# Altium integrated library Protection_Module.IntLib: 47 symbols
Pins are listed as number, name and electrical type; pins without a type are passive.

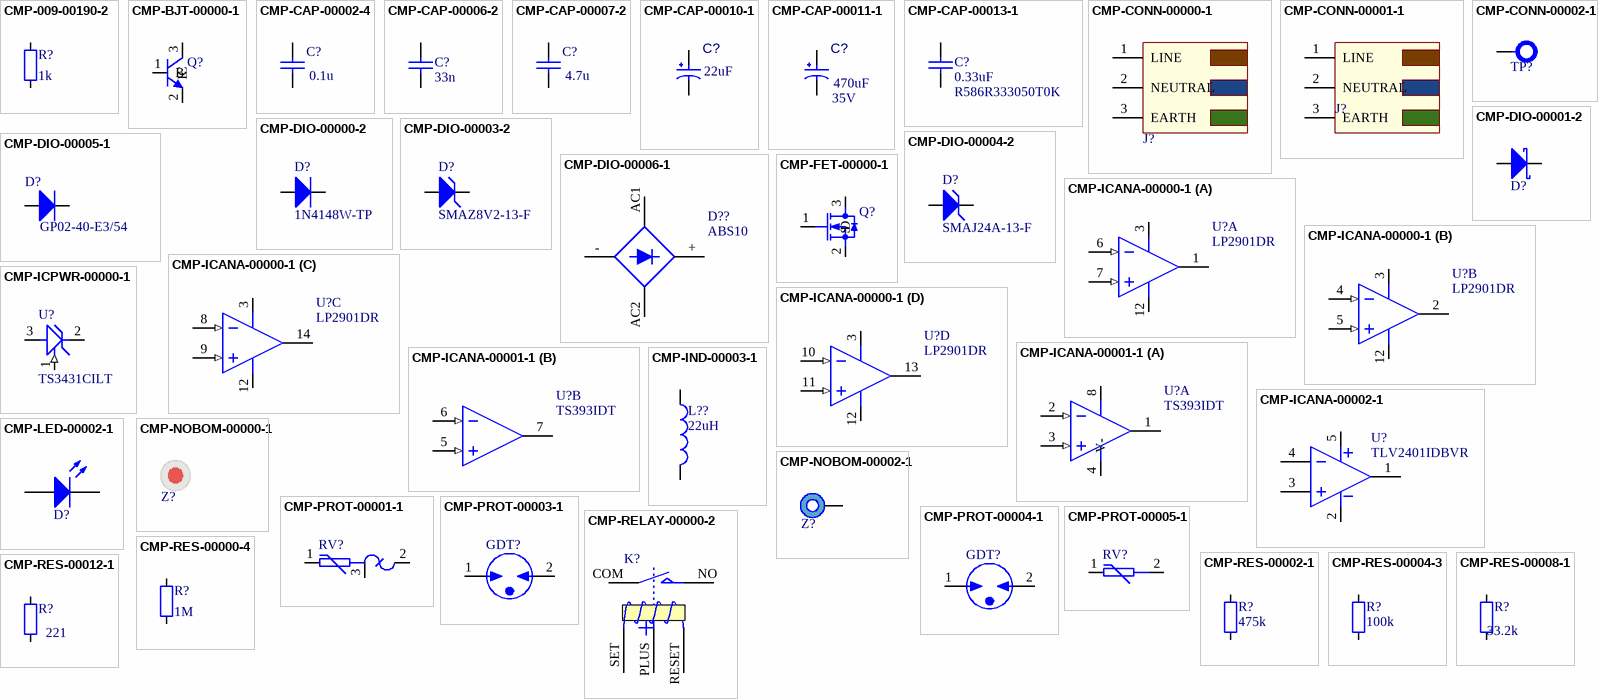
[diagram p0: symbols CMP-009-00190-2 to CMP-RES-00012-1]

## CMP-009-00190-2
designator R?, comment value 1k  (hidden comment: ERJ-3EKF1001V)
Res Thick Film 0603 1K Ohm 1% 1/10W ±100ppm/°C Molded SMD Punched Carrier T/R; Manufacturer: Panasonic; Voltage Rating: 75V; Power: 100mW
footprint RESC1608X05AN,0603, (Chip Resistor, Body 1.6x0.8mm, IPC Medium Density, 0603 imperial with minimal silk)
footprint RESC1608X60,0603,L (Chip Resistor, Body 1.6x0.8mm, IPC High Density, 0603 imperial)
footprint RESC1608X05AN[0603] (Chip Resistor, Body 1.6x0.8mm, IPC Medium Density, 0603 imperial with silk box)
pins: 1, 2
1 alternate drawing of the same symbol

## CMP-BJT-00000-1
designator Q?, comment BCV72,215  (value not drawn)
BCV72 Series 60 V 100 mA 250 mW NPN SMT General Purpose Transistor - SOT-23; Manufacturer: Nexperia; Collector Emitter Voltage (VCEO): 60V; Collector Base Voltage (VCBO): 80V; Frequency: 100MHz; Max Collector Current: 100mA
footprint SOT95P275X125-3N (SOT23, 3-Leads, Body 2.90x2.75mm, Pitch 0.95mm, IPC Medium Density)
pins: 1 B, 2 E, 3 C

## CMP-CAP-00002-4
designator C?, comment value 0.1u  (hidden comment: CL10B104KB8NNNL)
Multilayer Ceramic Capacitor, 0.1 uF, 50 V, ± 10%, X7R, 0603 [1608 Metric]; Manufacturer: Samsung; Voltage Rating: 50V; Material: 4241
footprint CAPC1608X09N,0603, (Chip Capacitor, Body 1.6x0.8mm, IPC Medium Density, 0603 imperial with minimal silk)
footprint CAPC1608X100N,0603,L (Chip Capacitor, Body 1.6x0.8mm, IPC High Density, 1.0 mm height, 0603 imperial)
footprint CAPC1608X09N[0603] (Chip Capacitor, Body 1.6x0.8mm, IPC Medium Density, 0603 imperial with silk box)
pins: 1, 2

## CMP-CAP-00006-2
designator C?, comment value 33n  (hidden comment: CL10B333KB8NNNC)
Multilayer Ceramic Capacitor, 0.033 uF, 50 V, ± 10%, X7R, 0603 [1608 Metric]; Manufacturer: Samsung; Voltage Rating: 50V
footprint CAPC1608X09N,0603, (Chip Capacitor, Body 1.6x0.8mm, IPC Medium Density, 0603 imperial with minimal silk)
footprint CAPC1608X100N,0603,L (Chip Capacitor, Body 1.6x0.8mm, IPC High Density, 1.0 mm height, 0603 imperial)
footprint CAPC1608X09N[0603] (Chip Capacitor, Body 1.6x0.8mm, IPC Medium Density, 0603 imperial with silk box)
pins: 1, 2

## CMP-CAP-00007-2
designator C?, comment value 4.7u  (hidden comment: CL10A475KA8NQNC)
Multilayer Ceramic Capacitor, 4.7 uF, 25 V, ± 10%, X5R, 0603 [1608 Metric]; Manufacturer: Samsung; Voltage Rating: 25V; Dielectric: X7R
footprint CAPC1608X09N,0603, (Chip Capacitor, Body 1.6x0.8mm, IPC Medium Density, 0603 imperial with minimal silk)
footprint CAPC1608X100N,0603,L (Chip Capacitor, Body 1.6x0.8mm, IPC High Density, 1.0 mm height, 0603 imperial)
footprint CAPC1608X09N[0603] (Chip Capacitor, Body 1.6x0.8mm, IPC Medium Density, 0603 imperial with silk box)
pins: 1, 2

## CMP-CAP-00010-1
designator C?, comment value 22uF  (hidden comment: ESH226M035AC3AA)
Cap Aluminum Lytic 22uF 35V 20% (5 X 11mm) Radial 2mm 65mA 2000h 105C Bulk; Manufacturer: KEMET; Life (Hours): 2000Hour
footprint CAP_RAD2P_CYL_5X13 (Radial electrolytic 2 mm pitch 5 mm dia 12.5 mm high with + and - terminals.)
pins: +, -

## CMP-CAP-00011-1
designator C?, comment value 470uF  Voltage Rating (DC): 35V  (hidden comment: ESH477M035AH3AA)
Capacitor; Al Electrolytic; Cap 470 uF; Tol 20%; Vol-Rtg 35 VDC; Radial; 10x17 mm; Manufacturer: KEMET; Dissipation Factor: 0.14%; Life (Hours): 2000Hour
footprint CAP_RAD5P_CYL_10X20 (Radial electrolytic 5 mm pitch 10 mm dia, 20 mm high with + and - terminals.)
pins: +, -

## CMP-CAP-00013-1
designator C?, comment R586R333050T0K  value 0.33uF
CAP FILM 600VAC(X1) 0.33 UF 10%; Manufacturer: KEMET
footprint CAP_RAD28P3213X22 (Box capacitor 27.5 mm pin pitch, 31.5 mm length, 13 mm width, 22 mm height)
pins: 1, 2

## CMP-CONN-00000-1
designator J?, comment 703W-00/54  (value not drawn)
Conn Electrical Power Inlet Right Angled Pin Cont 3 Cond 3 Poles Solder 250V; Manufacturer: Qualtek
footprint QUALTEK_703W-00/54 (Mains power inlet IEC 320-C14 with 9 mm pin pitch.)
pins: 1 LINE, 2 NEUTRAL, 3 EARTH

## CMP-CONN-00001-1
designator J?, comment PX0675/PC  (value not drawn)
Conn Electrical Power Outlet Right Angled Pin Cont 3 Cond 3 Poles Solder 250V; Manufacturer: Bulgin
footprint BULGIN_PX0675/PC (Mains power inlet IEC 320-F (like a C13, but panel mount) with 7 mm pin pitch.)
pins: 1 LINE, 2 NEUTRAL, 3 EARTH

## CMP-CONN-00002-1
designator TP?, comment KEYSTONE_5010  (value not drawn)
Through hole test point, red; Manufacturer: Keystone Electronics; Manufacturer Part Number: 5010; Hole Diameter: 1.6mm
footprint KEYSTONE_5010 (TEST POINT PC MULTIPURPOSE RED)
pins: 1

## CMP-DIO-00000-2
designator D?, comment 1N4148W-TP
Rectifier Diode Switching 100V 0.3A 4ns 2-Pin SOD-123 T/R / DIODE GEN PURP 100V 150MA SOD123; Manufacturer: MCC; Forward Voltage: 1V; Power Dissipation: 400mW
footprint SOD-123 (SOD-123 SMD diode with A and K pads)
pins: A, K

## CMP-DIO-00001-2
designator D?, comment MBR130T1G  (value not drawn)
DIODE SCHOTTKY 30V 1A SOD123 / Rectifier Diode Schottky 30V 1A 2-Pin SOD-123 T/R; Manufacturer: ON Semiconductor; Power Dissipation: 400mW; Reverse Recovery Time: 4ns; Forward Voltage: 470mV
footprint SOD-123 (SOD-123 SMD diode with A and K pads)
pins: A, K

## CMP-DIO-00003-2
designator D?, comment SMAZ8V2-13-F
DIODE ZENER 8.2V 1W SMA; Manufacturer: Diodes; Reverse Recovery Time: 1.8us; Forward Current: 1A; Forward Voltage: 1.2V
footprint DO-214AC (SMA Molded Diode, 2-Leads, Body 4.30x2.61mm, IPC Medium Density with A and K pads)
pins: A, K

## CMP-DIO-00004-2
designator D?, comment SMAJ24A-13-F
SMAJ24A Series 400 W 24 V Surface Mount Uni-Directional TVS Diode - DO-214AC; Manufacturer: Diodes; Forward Current: 1A; Power Dissipation: 400W; Forward Voltage: 1.2V; Reverse Recovery Time: 1.8us; Voltage Rating (DC): 24V
footprint DO-214AC (SMA Molded Diode, 2-Leads, Body 4.30x2.61mm, IPC Medium Density with A and K pads)
pins: A, K

## CMP-DIO-00005-1
designator D?, comment GP02-40-E3/54
Rectifier Diode Switching 4KV 0.25A 2000ns 2-Pin DO-41 T/R / DIODE GEN PURP 4KV 250MA DO204; Manufacturer: Vishay; Reverse Recovery Time: 2usec; Forward Voltage: 3V; Voltage Rating (DC): 4000V
footprint DO-204AL (TH diode (DO-41), 10.16 mm pitch, with A and K pads)
pins: A, K

## CMP-DIO-00006-1
designator D??, comment ABS10
Bridge Rectifier Abs/Sopa-4 T&r 5K Rohs Compliant: Yes; Manufacturer: SMC; Manufacturer Part Number: ABS10TR; Manufacturer: Diotec; Manufacturer: Diodes; Manufacturer Part Number: ABS10A-13
footprint SOP400P640X170-4N_BRIDGE (Bridge Rectifier SOPA-4, SOP, 4-Leads, Body 5.05x4.40mm, Pitch 4.00mm, IPC Medium Density)
pins: +, -, AC1, AC2

## CMP-FET-00000-1
designator Q?, comment IRLML6346TRPBF  (value not drawn)
MOSFET Transistor, N Channel, 3.4 A, 30 V, 0.046 ohm, 4.5 V, 800 mV; Manufacturer: Infineon; Drain to Source Voltage (Vdss): 30V; Continuous Drain Current (ID): 3.4A; Drain to Source Resistance: 46mR
footprint SOT95P275X125-3N (SOT23, 3-Leads, Body 2.90x2.75mm, Pitch 0.95mm, IPC Medium Density)
pins: 1 G, 2 S, 3 D

## CMP-ICANA-00000-1
designator U?, comment LP2901DR
Quad low-power industrial grade standard comparator 14-SOIC -40 to 85; Manufacturer: Texas Instruments; Min Supply Voltage: 3V; Max Supply Voltage: 30V
footprint SOIC127P600X175-14N (SOIC, 14-Leads, Body 8.65x3.90mm, Pitch 1.27mm, IPC Medium Density, SO-14)
part A pins: 1 OUT1, 3 V+ (power), 6 IN1- (in), 7 IN1+ (in), 12 V- (power)
part B pins: 2 OUT2, 3 V+ (power), 4 IN2- (in), 5 IN2+ (in), 12 V- (power)
part C pins: 3 V+ (power), 8 IN3- (in), 9 IN3+ (in), 12 V- (power), 14 OUT3
part D pins: 3 V+ (power), 10 IN4- (in), 11 IN4+ (in), 12 V- (power), 13 OUT4

## CMP-ICANA-00001-1
designator U?, comment TS393IDT
Micropower CMOS dual voltage comparator, 9µA, 16V, -40, 0 to 125, 70°C, SO-8, Tape and Reel; Manufacturer: STMicroelectronics; Min Supply Voltage: 2.7V
footprint SOIC127P600X175-8N (SOIC, 8-Leads, Body 4.90x3.90mm, Pitch 1.27mm, IPC Medium Density, SO-8)
part A pins: 1 OUT1, 2 IN1- (in), 3 IN1+ (in), 4 V- (power), 8 V+ (power)
part B pins: 5 IN2+ (in), 6 IN2- (in), 7 OUT2

## CMP-ICANA-00002-1
designator U?, comment TLV2401IDBVR
Op Amp Single Low Power Amplifier R-R I/O ±8V/16V 5-Pin SOT-23 T/R; Manufacturer: Texas Instruments; Bandwidth: 5.5kHz; Max Supply Voltage: 16V; Min Supply Voltage: 2.5V
footprint SOT95P280X145-5N (SOT23, 5-Leads, Body 2.90x2.80mm, Pitch 0.95mm, IPC Medium Density)
pins: 1 OUT, 2 -Vs, 3 +IN, 4 -IN, 5 +Vs

## CMP-ICPWR-00000-1
designator U?, comment TS3431CILT
V-Ref Adjustable 1.24V to 24V 100mA 3-Pin SOT-23 T/R; Manufacturer: STMicroelectronics; Max Supply Voltage: 25V; Tolerance: 0.25%
footprint SOT95P275X125-3N (SOT23, 3-Leads, Body 2.90x2.75mm, Pitch 0.95mm, IPC Medium Density)
pins: 1 VREF (in), 2 K, 3 A

## CMP-IND-00003-1
designator L??, comment value 22uH  (hidden comment: SRP1265CC-220M)
Inductor Power Shielded Wirewound 22uH 20% 100KHz 20Q-Factor Carbonyl Powder 10A 0.037Ohm DCR; Manufacturer: Bourns
footprint INDUCTOR-BOURNS_SRP1265CC (SMT inductor 12 mm square, 6.5 mm high, with 4.7 mm wide terminals)
pins: 1, 2
1 alternate drawing of the same symbol

## CMP-LED-00002-1
designator D?, comment LTST-C191KRKT  (value not drawn)
LED Uni-Color Red 639nm 2-Pin Chip LED T/R / LED RED CLEAR 0603 SMD; Manufacturer: Vishay Lite-On; Forward Voltage: 2V; Forward Current: 30mA; Viewing Angle: 130°
footprint LEDC1608X06NRED,0603, (Chip LED Body 1.6x0.8mm, IPC Medium Density, red)
pins: A, K

## CMP-NOBOM-00000-1
designator Z?, comment FIDUCIAL_1_3  (value not drawn)  (no BOM)
Fiducial 1 mm copper, 3 mm solder mask, two footprint options.
footprint FIDUCIAL_1_3_KEEPOUT (1mm dia fiducial with 3mm dia keepout)
footprint FIDUCIAL_1_3 (1mm dia fiducial with 3mm dia solder mask opening)

## CMP-NOBOM-00002-1
designator Z?, comment MOUNTING_HOLE_5MM  (value not drawn)  (no BOM)
5 mm diameter plated mounting hole with 8 mm diameter copper surround
footprint MOUNT_HOLE_5MM_8MM (Hole sized for a 5 mm screw, with 8 mm copper surrounding.)
pins: 0

## CMP-PROT-00001-1
designator RV?, comment TMOV20RP300M  (value not drawn)
Var MOV 300VAC/385VDC 10000A 517V Radial Bulk; Manufacturer: Littelfuse; Varistor Voltage: 470V; Clamping Voltage: 775V; Voltage Rating (AC): 300V
footprint LITTELFUSE_ITMOV_20MM (MOV with thermal fusing and indicator lead)
pins: 1, 2, 3

## CMP-PROT-00003-1
designator GDT?, comment CG32.5L  (value not drawn)
Arrestor; 2500 V (min.) (breakdown); Rugged Ceramic-metal Package; 1 Pf (max.); Manufacturer: Littelfuse; Breakdown Voltage: 2.5kV
footprint LITTELFUSE_CG3x (for gas discharge tubes and other wide axial components)
pins: 1, 2

## CMP-PROT-00004-1
designator GDT?, comment CG31.0L  (value not drawn)
CG3 Series - Two Terminal High Voltage Gas Plasma Arresters, 1000V, 10kA, plug in, RoHS; Manufacturer: Littelfuse; Breakdown Voltage: 1.0kV
footprint LITTELFUSE_CG3x (for gas discharge tubes and other wide axial components)
pins: 1, 2

## CMP-PROT-00005-1
designator RV?, comment TMOV20RP300E  (value not drawn)
Thermally Protected Varistor 300 V RMS 775 V Clamp 10000 A 800 pF Radial Lead; Manufacturer: Littelfuse; Manufacturer: Eaton; Manufacturer Part Number: MOVTP20V300N; Voltage Rating (AC): 300V; Varistor Voltage: 517V
footprint MOV_RAD7.5P5.5S_DISC_20X11.5 (MOV radial disc, 7.5 mm pitch with 5.5 mm offset, 20 mm dia. 11.5 mm thick, max height 26 mm.)
pins: 1, 2

## CMP-RELAY-00000-2
designator K?, comment TE_CONN_2-1415898-5  (value not drawn)
Electromechanical Relay SPST-NO 16A 12VDC 240Ohm Through Hole; Manufacturer: TE Connectivity P&B; Contact Voltage Rating (AC): 250V; Coil Power: 600mW; Throw Configuration: SPST
footprint TE_RT1_2COIL_LATCHING (TE Connectivity/Schrack RT1/RT3 type latching SPST relay)
pins: COM, NO, PLUS, RESET, SET

## CMP-RES-00000-4
designator R?, comment value 1M  (hidden comment: ERJ-3EKF1004V)
Res Thick Film 0603 1M Ohm 1% 1/10W ±100ppm/°C Molded SMD Punched Carrier T/R; Manufacturer: Panasonic; Voltage Rating (DC): 75V; Max Power Dissipation: 100mW
footprint RESC1608X05AN,0603, (Chip Resistor, Body 1.6x0.8mm, IPC Medium Density, 0603 imperial with minimal silk)
footprint RESC1608X60,0603,L (Chip Resistor, Body 1.6x0.8mm, IPC High Density, 0603 imperial)
footprint RESC1608X05AN[0603] (Chip Resistor, Body 1.6x0.8mm, IPC Medium Density, 0603 imperial with silk box)
pins: 1, 2
1 alternate drawing of the same symbol

## CMP-RES-00002-1
designator R?, comment value 475k  (hidden comment: ERJ-3EKF4753V)
SMD Chip Resistor, 475 kOhm, ± 1%, 100 mW, 0603 [1608 Metric], Thick Film, Precision; Manufacturer: Panasonic; Max Power Dissipation: 100mW; Voltage Rating: 75V; Temperature Coefficient: 100ppm/°C
footprint RESC1608X05AN,0603, (Chip Resistor, Body 1.6x0.8mm, IPC Medium Density, 0603 imperial with minimal silk)
footprint RESC1608X60,0603,L (Chip Resistor, Body 1.6x0.8mm, IPC High Density, 0603 imperial)
footprint RESC1608X05AN[0603] (Chip Resistor, Body 1.6x0.8mm, IPC Medium Density, 0603 imperial with silk box)
pins: 1, 2
1 alternate drawing of the same symbol

## CMP-RES-00004-3
designator R?, comment value 100k  (hidden comment: ERJ-3EKF1003V)
Resistor Thick Film 0603 100K Ohm 1% 1/10W 100ppm/C Molded SMD Punched Carrier T/R; Manufacturer: Panasonic; Max Power Dissipation: 100mW; Voltage Rating (DC): 75V; Temperature Coefficient: 100ppm/°C
footprint RESC1608X05AN,0603, (Chip Resistor, Body 1.6x0.8mm, IPC Medium Density, 0603 imperial with minimal silk)
footprint RESC1608X60,0603,L (Chip Resistor, Body 1.6x0.8mm, IPC High Density, 0603 imperial)
footprint RESC1608X05AN[0603] (Chip Resistor, Body 1.6x0.8mm, IPC Medium Density, 0603 imperial with silk box)
pins: 1, 2
1 alternate drawing of the same symbol

## CMP-RES-00008-1
designator R?, comment value 33.2k  (hidden comment: ERJ-3EKF3322V)
Res Thick Film 0603 33.2K Ohm 1% 1/10W +/-100ppm/ßC Molded SMD Punched Carrier T/R; Manufacturer: Panasonic; Voltage Rating: 50V; Power: 100mW; Temperature Coefficient: 100ppm/°C
footprint RESC1608X05AN,0603, (Chip Resistor, Body 1.6x0.8mm, IPC Medium Density, 0603 imperial with minimal silk)
footprint RESC1608X60,0603,L (Chip Resistor, Body 1.6x0.8mm, IPC High Density, 0603 imperial)
footprint RESC1608X05AN[0603] (Chip Resistor, Body 1.6x0.8mm, IPC Medium Density, 0603 imperial with silk box)
pins: 1, 2
1 alternate drawing of the same symbol

## CMP-RES-00012-1
designator R?, comment value 221  (hidden comment: ERJ-3EKF2210V)
SMD Chip Resistor, 221 Ohm, ± 1%, 100 mW, 0603 [1608 Metric], Thick Film, Precision; Manufacturer: Panasonic; Temperature Coefficient: 100ppm/°C; Voltage Rating: 75V; Power Rating: 100mW
footprint RESC1608X05AN,0603, (Chip Resistor, Body 1.6x0.8mm, IPC Medium Density, 0603 imperial with minimal silk)
footprint RESC1608X60,0603,L (Chip Resistor, Body 1.6x0.8mm, IPC High Density, 0603 imperial)
footprint RESC1608X05AN[0603] (Chip Resistor, Body 1.6x0.8mm, IPC Medium Density, 0603 imperial with silk box)
pins: 1, 2
1 alternate drawing of the same symbol

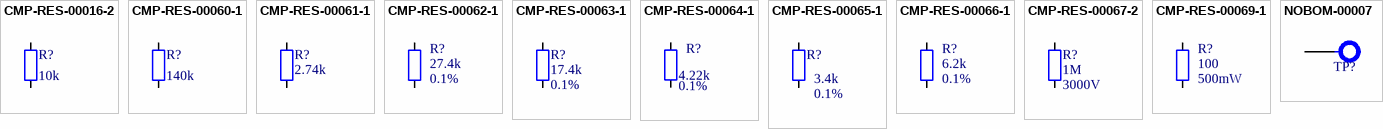
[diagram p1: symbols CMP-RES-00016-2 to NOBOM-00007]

## CMP-RES-00016-2
designator R?, comment value 10k  (hidden comment: RMCF0603FT10K0)
Res Thick Film 0603 10K Ohm 1% 1/10W ±100ppm/°C Molded SMD SMD Paper T/R; Manufacturer: Stackpole Electronics; Max Power Dissipation: 100mW; Voltage Rating (DC): 75V
footprint RESC1608X05AN,0603, (Chip Resistor, Body 1.6x0.8mm, IPC Medium Density, 0603 imperial with minimal silk)
footprint RESC1608X60,0603,L (Chip Resistor, Body 1.6x0.8mm, IPC High Density, 0603 imperial)
footprint RESC1608X05AN[0603] (Chip Resistor, Body 1.6x0.8mm, IPC Medium Density, 0603 imperial with silk box)
pins: 1, 2
1 alternate drawing of the same symbol

## CMP-RES-00060-1
designator R?, comment value 140k  (hidden comment: RMCF0603FT140K)
Res Thick Film 0603 140K Ohm 1% 1/10W ±100ppm/°C Molded SMD SMD Paper T/R; Manufacturer: Stackpole Electronics; Voltage Rating (DC): 75V; Power: 100mW
footprint RESC1608X05AN,0603, (Chip Resistor, Body 1.6x0.8mm, IPC Medium Density, 0603 imperial with minimal silk)
footprint RESC1608X60,0603,L (Chip Resistor, Body 1.6x0.8mm, IPC High Density, 0603 imperial)
footprint RESC1608X05AN[0603] (Chip Resistor, Body 1.6x0.8mm, IPC Medium Density, 0603 imperial with silk box)
pins: 1, 2
1 alternate drawing of the same symbol

## CMP-RES-00061-1
designator R?, comment value 2.74k  (hidden comment: RMCF0603FT2K74)
Res Thick Film 0603 2.74K Ohm 1% 1/10W ±100ppm/°C Molded SMD SMD Paper T/R; Manufacturer: Stackpole Electronics; Voltage Rating: 75V; Power Rating: 100mW
footprint RESC1608X05AN,0603, (Chip Resistor, Body 1.6x0.8mm, IPC Medium Density, 0603 imperial with minimal silk)
footprint RESC1608X60,0603,L (Chip Resistor, Body 1.6x0.8mm, IPC High Density, 0603 imperial)
footprint RESC1608X05AN[0603] (Chip Resistor, Body 1.6x0.8mm, IPC Medium Density, 0603 imperial with silk box)
pins: 1, 2
1 alternate drawing of the same symbol

## CMP-RES-00062-1
designator R?, comment value 27.4k  Tolerance: 0.1%  (hidden comment: ERA-3AEB2742V)
Res Thin Film 0603 27.4K Ohm 0.1% 0.1W(1/10W) ±25ppm/C Pad SMD Automotive T/R; Manufacturer: Panasonic; Power: 100mW; Temperature Coefficient: 25ppm/°C; Voltage Rating: 75V
footprint RESC1608X05AN,0603, (Chip Resistor, Body 1.6x0.8mm, IPC Medium Density, 0603 imperial with minimal silk)
footprint RESC1608X60,0603,L (Chip Resistor, Body 1.6x0.8mm, IPC High Density, 0603 imperial)
footprint RESC1608X05AN[0603] (Chip Resistor, Body 1.6x0.8mm, IPC Medium Density, 0603 imperial with silk box)
pins: 1, 2
1 alternate drawing of the same symbol

## CMP-RES-00063-1
designator R?, comment value 17.4k  Tolerance: 0.1%  (hidden comment: ERA-3AEB1742V)
Res Thin Film 0603 17.4K Ohm 0.1% 0.1W(1/10W) ±25ppm/C Pad SMD Automotive T/R; Manufacturer: Panasonic; Max Power Dissipation: 100mW; Voltage Rating (DC): 75V; Temperature Coefficient: 25ppm/°C
footprint RESC1608X05AN,0603, (Chip Resistor, Body 1.6x0.8mm, IPC Medium Density, 0603 imperial with minimal silk)
footprint RESC1608X60,0603,L (Chip Resistor, Body 1.6x0.8mm, IPC High Density, 0603 imperial)
footprint RESC1608X05AN[0603] (Chip Resistor, Body 1.6x0.8mm, IPC Medium Density, 0603 imperial with silk box)
pins: 1, 2
1 alternate drawing of the same symbol

## CMP-RES-00064-1
designator R?, comment value 4.22k  Tolerance: 0.1%  (hidden comment: ERA-3AEB4221V)
Res Thin Film 0603 4.22K Ohm 0.1% 1/10W ±25ppm/°C Molded SMD SMD Punched Carrier T/R; Manufacturer: Panasonic; Max Power Dissipation: 100mW; Voltage Rating: 75V
footprint RESC1608X05AN,0603, (Chip Resistor, Body 1.6x0.8mm, IPC Medium Density, 0603 imperial with minimal silk)
footprint RESC1608X60,0603,L (Chip Resistor, Body 1.6x0.8mm, IPC High Density, 0603 imperial)
footprint RESC1608X05AN[0603] (Chip Resistor, Body 1.6x0.8mm, IPC Medium Density, 0603 imperial with silk box)
pins: 1, 2
1 alternate drawing of the same symbol

## CMP-RES-00065-1
designator R?, comment value 3.4k  Tolerance: 0.1%  (hidden comment: ERA-3AEB3401V)
Res Thin Film 0603 3.4K Ohm 0.1% 0.1W(1/10W) ±25ppm/C Pad SMD Automotive T/R; Manufacturer: Panasonic; Power: 100mW; Temperature Coefficient: 25ppm/°C; Voltage Rating: 75V
footprint RESC1608X05AN,0603, (Chip Resistor, Body 1.6x0.8mm, IPC Medium Density, 0603 imperial with minimal silk)
footprint RESC1608X60,0603,L (Chip Resistor, Body 1.6x0.8mm, IPC High Density, 0603 imperial)
footprint RESC1608X05AN[0603] (Chip Resistor, Body 1.6x0.8mm, IPC Medium Density, 0603 imperial with silk box)
pins: 1, 2
1 alternate drawing of the same symbol

## CMP-RES-00066-1
designator R?, comment value 6.2k  Tolerance: 0.1%  (hidden comment: ERA-3AEB622V)
Res Thin Film 0603 6.2K Ohm 0.1% 1/10W ±25ppm/°C Molded SMD SMD Punched Carrier T/R; Manufacturer: Panasonic; Max Power Dissipation: 100mW; Voltage Rating: 75V
footprint RESC1608X05AN,0603, (Chip Resistor, Body 1.6x0.8mm, IPC Medium Density, 0603 imperial with minimal silk)
footprint RESC1608X60,0603,L (Chip Resistor, Body 1.6x0.8mm, IPC High Density, 0603 imperial)
footprint RESC1608X05AN[0603] (Chip Resistor, Body 1.6x0.8mm, IPC Medium Density, 0603 imperial with silk box)
pins: 1, 2
1 alternate drawing of the same symbol

## CMP-RES-00067-2
designator R?, comment value 1M  Voltage Rating: 3000V  (hidden comment: CHV2512-FX-1004ELF)
SMD Chip Resistor, 1 MOhm, ± 1%, 1 W, 2512 [6332 Metric], Thick Film, High Voltage; Manufacturer: Bourns JW Miller; Max Power Dissipation: 1.0W; Temperature Coefficient: 100ppm/°C
footprint RESC6534X70,2512, (Chip Resistor, 2-Leads, Body 6.5x3.4mm, IPC Medium Density, Height 0.75 mm, 2512 imperial, minimal silk)
footprint RESC6534X70[2512] (Chip Resistor, 2-Leads, Body 6.5x3.4mm, IPC Medium Density, Height 0.75 mm, 2512 imperial, silk box)
pins: 1, 2
1 alternate drawing of the same symbol

## CMP-RES-00069-1
designator R?, comment value 100  Power: 500mW  (hidden comment: ERJ-P06F1000V)
SMD Chip Resistor, 100 Ohm, ± 1%, 500 mW, 0805 [2012 Metric], Thick Film, Anti-Surge; Manufacturer: Panasonic; Temperature Coefficient: 100ppm/°C; Voltage Rating: 150V
footprint RESC2012X06N,0805, (Chip Resistor, 2-Leads, Body 2.00x1.20mm, IPC Medium Density, 0805 imperial, minimal silk)
footprint RESC2012X06N[0805] (Chip Resistor, 2-Leads, Body 2.00x1.20mm, IPC Medium Density, 0805 imperial, silk box)
pins: 1, 2
1 alternate drawing of the same symbol

## NOBOM-00007
designator TP?, comment TP TH  0.78mm  (value not drawn)  (no BOM)
Test point, TH, 0.78mm (30mil) hole, 1.27mm (50 mil) pad; partnumber: NOBOM-00007; manufacturer: New Horizons; id: 137437
footprint TP_TH078H127P
pins: 1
